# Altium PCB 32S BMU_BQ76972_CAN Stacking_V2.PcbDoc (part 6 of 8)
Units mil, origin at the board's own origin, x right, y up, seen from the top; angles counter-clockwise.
Board outline 7319.29 x 5216.54 mil, 4 copper layers (Top Layer, Layer 1, Layer 2, Bottom Layer), stack 73.068 mil thick; 811 components, 524 nets, 2320 pads, 2669 vias.
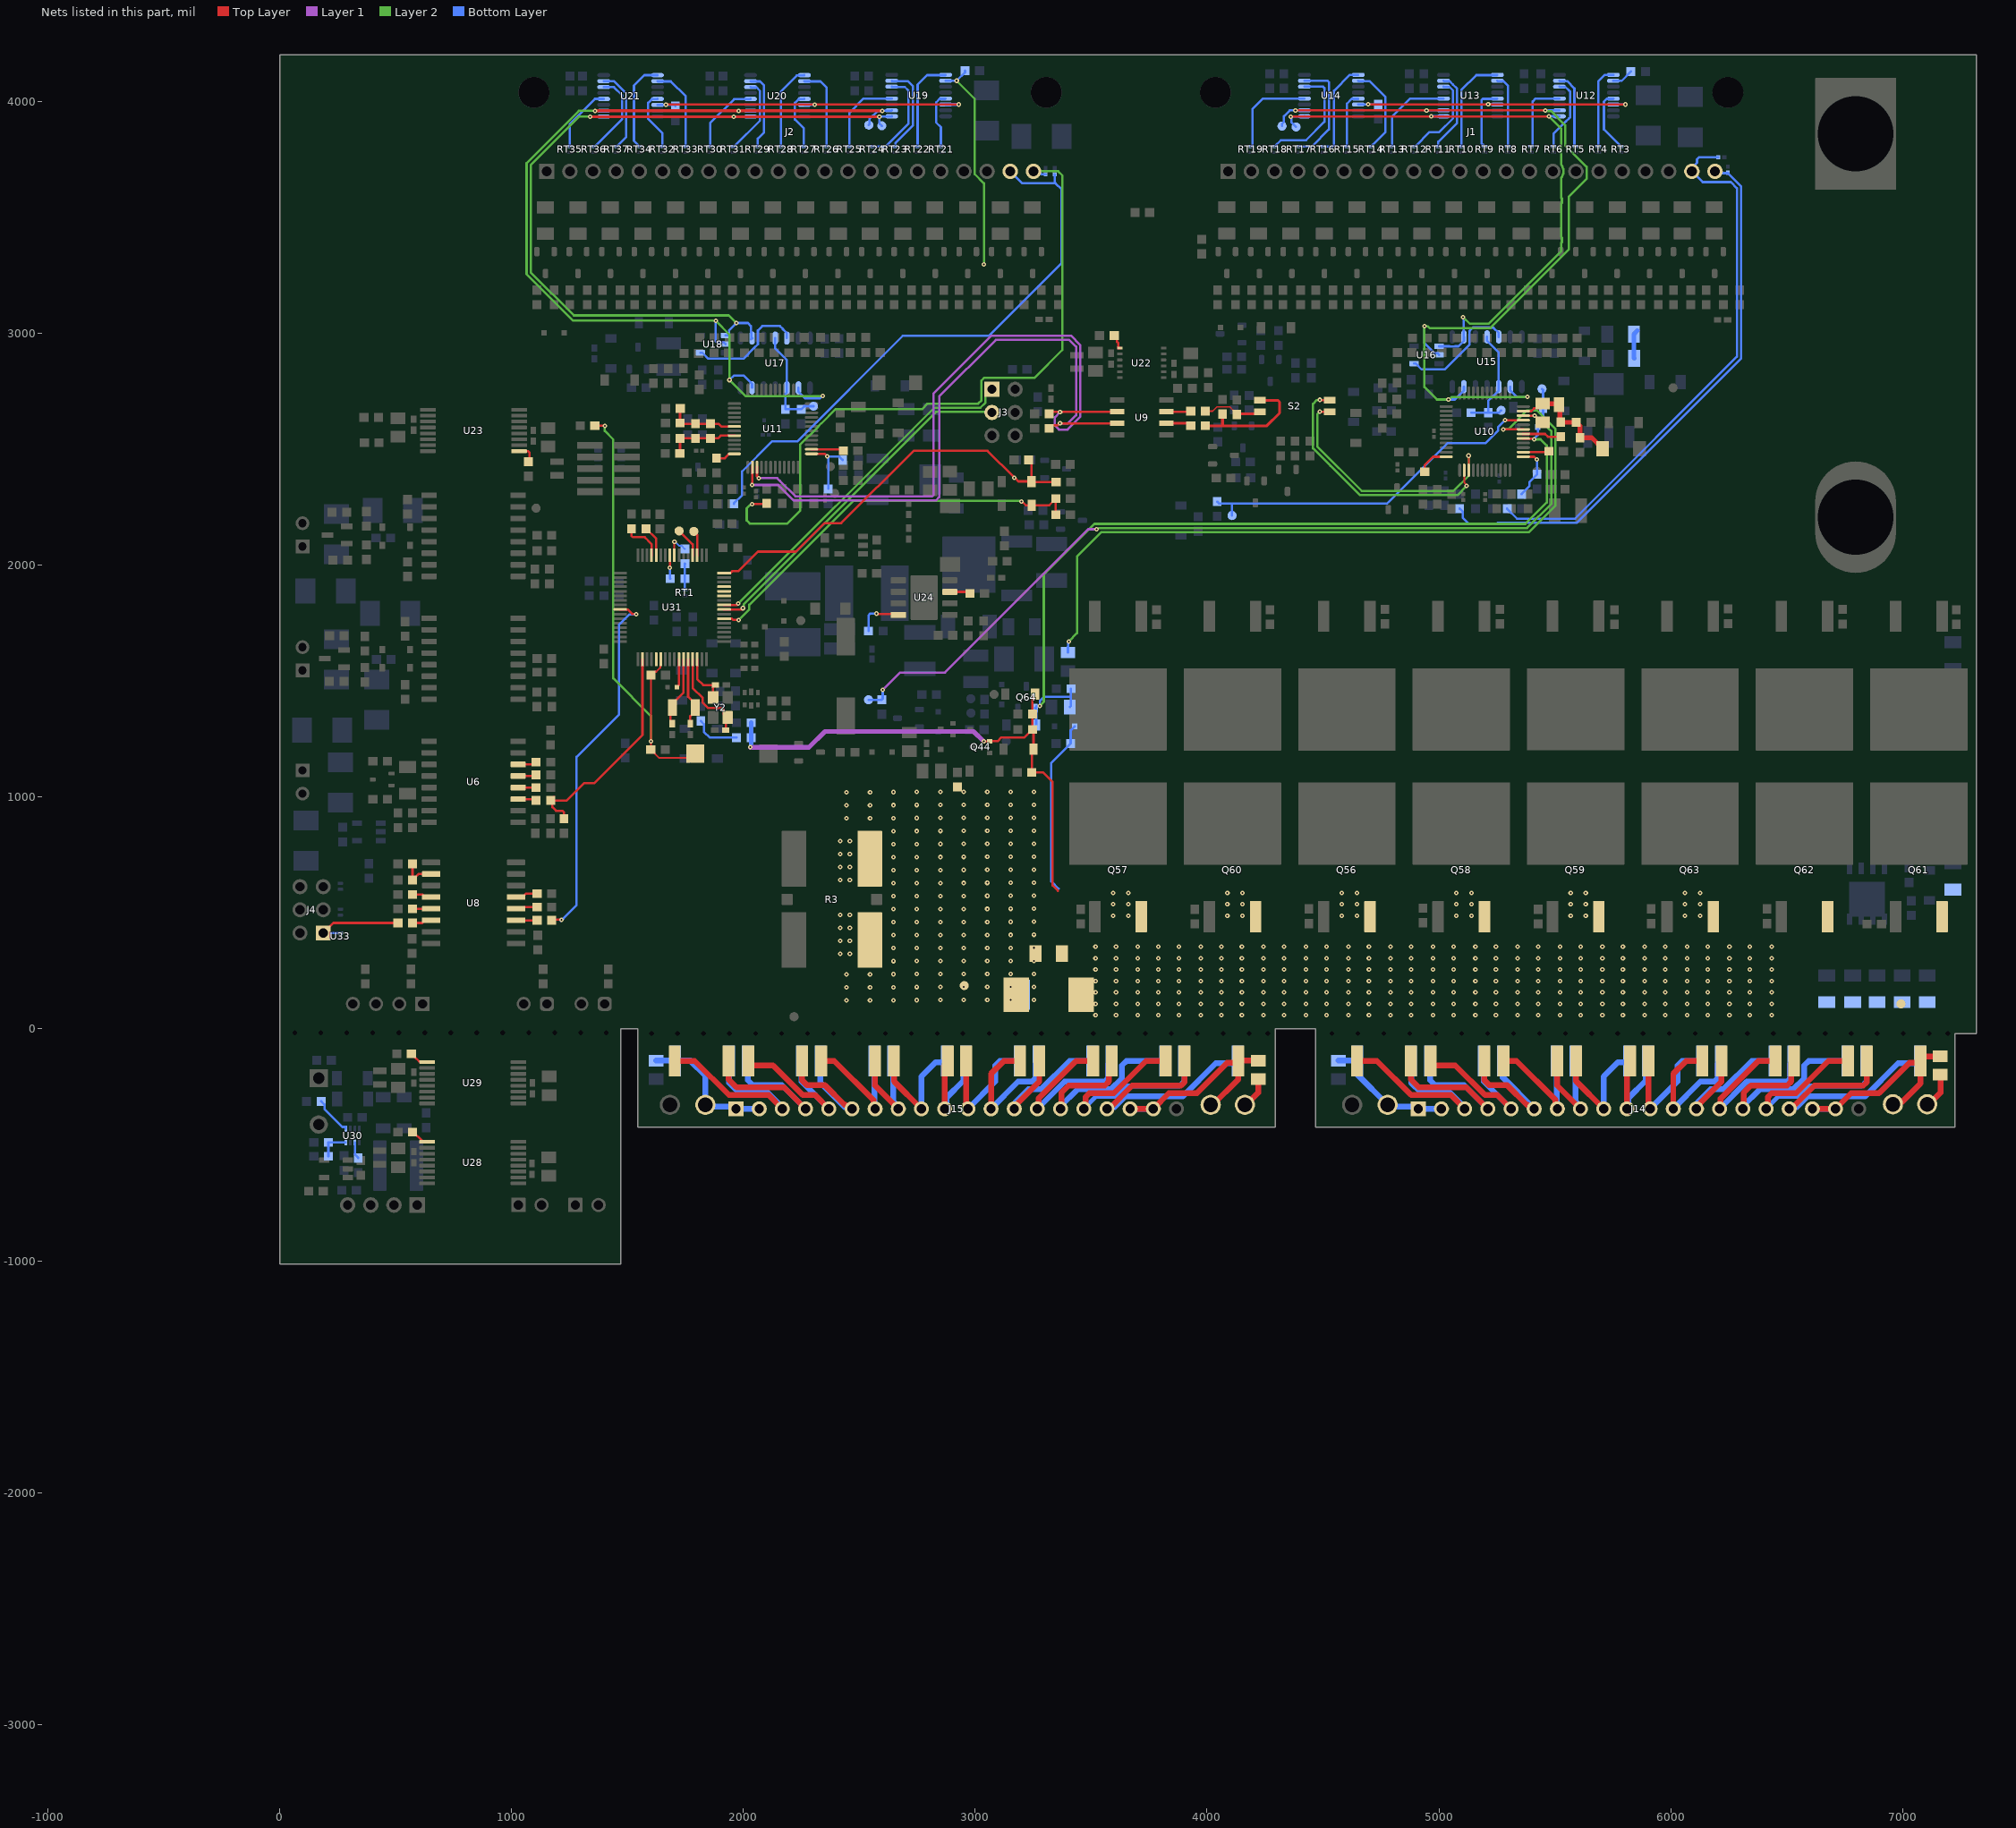
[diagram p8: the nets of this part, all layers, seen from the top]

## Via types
v1: diameter 19.68, hole 7.87, Top Layer to Bottom Layer, tented both sides, 2668 vias
v2: diameter 40, hole 20, Top Layer to Bottom Layer, 1 vias

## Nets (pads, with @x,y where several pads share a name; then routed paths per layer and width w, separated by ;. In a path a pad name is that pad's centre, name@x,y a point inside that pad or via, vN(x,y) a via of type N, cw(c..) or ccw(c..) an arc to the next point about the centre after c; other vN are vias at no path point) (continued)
NetR22_2: R22.2 U31.8 | length 115.6
  Top Layer w8: U31.8@1702.62,2043.51 1702.62,2101 v1(1702.76,2101.14)
  Bottom Layer w8: v1(1702.76,2101.14) 1705.92,2101.14 1722.68,2084.38 1733.72,2084.38 R22.2@1747.87,2070.22
NetR27_2: R27.2 U6.3 | length 79.6
  Top Layer w10: U6.3@1028.41,991.17 1100.41,991.17 R27.2@1105.8,985.78
NetR28_2: R28.2 U6.4 | length 77.5
  Top Layer w10: U6.4@1028.41,1041.17 1105.6,1041.17 R28.2@1105.8,1040.97
NetR30_2: R30.2 U6.5 | length 79.4
  Top Layer w10: U6.5@1028.41,1091.17 1100.82,1091.17 R30.2@1105.8,1096.16
NetR31_2: R31.2 U6.6 | length 81.6
  Top Layer w10: U6.6@1028.41,1141.17 1095.63,1141.17 R31.2@1105.8,1151.34
NetR35_2: R35.2 U8.3 | length 90.8
  Top Layer w10: U8.3@1019.56,468.59 R35.2@1110.35,468.59
NetR36_1: R36.1 U8.14 | length 85.2
  Top Layer w10: R36.1@572.94,457.22 614.49,457.22 625.85,468.59 U8.14@653.41,468.59
NetR37_2: R37.2 U8.4 | length 93.9
  Top Layer w10: U8.4@1019.56,518.59 1047.11,518.59 1054.71,526.18 R37.2@1110.35,526.18
NetR38_1: R38.1 U8.13 | length 80.5
  Top Layer w10: R38.1@572.94,518.59 U8.13@653.41,518.59
NetR39_2: R39.2 U8.12 | length 85.2
  Top Layer w10: R39.2@572.94,579.89 614.55,579.89 625.85,568.59 U8.12@653.41,568.59
NetR40_1: R40.1 U8.5 | length 97.1
  Top Layer w10: U8.5@1019.56,568.59 1047.11,568.59 1062.24,583.71 R40.1@1110.35,583.71
NetR41_1: R41.1 R51.2 S2.2 | length 264.3
  Top Layer w6: R51.2@3992.58,2664.85 4024.59,2664.85 4043.73,2683.99 4097.8,2683.99 4112.62,2669.17 4112.62,2666.8 4126.12,2653.31 R41.1@4128.32,2653.31
  Top Layer w10: R41.1@4128.32,2653.31 4222.93,2653.31 S2.2@4231.33,2661.7
NetR42_1: R42.1 R54.2 S2.1 | length 526.9
  Top Layer w12: R54.2@3992.58,2601.72 4066.99,2601.72 ; R42.1@4066.99,2653.31 4066.99,2601.72 ; S2.1@4231.33,2711.7 4305.27,2711.7 4312.95,2704.02 4312.95,2656.64 4258.04,2601.72 4066.99,2601.72
NetR45_1: R45.1 R52.2 U8.10 | length 160.5
  Top Layer w10: R52.2@572.94,711.67 R45.1@572.94,642.77 573.93,642.77 587.63,656.47 587.63,657.17 599.04,668.59 U8.10@653.41,668.59
NetR51_1: R51.1 U9.7 | length 105.5
  Top Layer w10: U9.7@3824.9,2662.79 3927.52,2662.79 R51.1@3929.58,2664.85
NetR54_1: R54.1 U9.6 | length 109.3
  Top Layer w10: U9.6@3824.9,2612.79 3918.52,2612.79 R54.1@3929.58,2601.72
NetR188_1: R188.1 U10.42 | length 166.3
  Top Layer w10: U10.42@5364.35,2566.69 5458.06,2566.69 5470.16,2554.6 R188.1@5525.62,2554.6
NetR189_1: R189.1 U10.38 | length 111.9
  Top Layer w10: U10.38@5364.35,2487.95 5470.09,2487.95 R189.1@5474.42,2492.28
NetR199_1: R199.1 U11.38 | length 139.6
  Top Layer w10: U11.38@2293.98,2500.45 2424.23,2500.45 R199.1@2430.82,2493.85
NetR201_1: R201.1 R209.2 | length 126
  Bottom Layer w20: R209.2@5842.67,2893.07 5840.96,2894.77 R201.1@5840.96,2997.22 R201.1@5855.94,3012.19
NetR211_1: R211.1 R229.1 U10.37 | length 240.2
  Top Layer w10: U10.37@5364.35,2468.27 5410.87,2468.27 v1(5423.07,2456.06)
  Bottom Layer w10: R211.1@5356.82,2307.06 5356.82,2308.05 5389.95,2341.18 5389.95,2358.41 5423.07,2391.54 R229.1@5423.07,2392.52 v1(5423.07,2456.06)
NetR218_1: R218.1 R248.1 U11.37 | length 287.6
  Top Layer w10: U11.37@2293.98,2480.76 2350.74,2480.76 v1@2362.26,2469.24
  Bottom Layer w10: R218.1@2365.93,2329.54 2365.93,2463.23 2362.26,2466.9 v1(2362.26,2469.52) 2412.63,2469.52 2413.58,2468.57 2414.57,2468.57 2428.27,2454.87 R248.1@2428.27,2453.88
NetR238_1: R238.1 U12.2 | length 92.3
  Bottom Layer w10: U12.2@5752.45,4090.16 5788.56,4090.16 R238.1@5828.28,4129.88
NetR257_2: R257.2 R301.2 TP22.1 U15.3 U15.11 | length 500.1
  Bottom Layer w10: R257.2@5139.35,2657.98 R301.2@5213,2657.98 ; U15.11@5207.86,2985.24 5207.86,2968.5 5257.86,2918.5 U15.3@5257.86,2770.67 5257.86,2753.94 5213,2709.08 R301.2@5213,2657.98 ; TP22.1@5268.67,2668.29 5258.36,2657.98 R301.2@5213,2657.98
NetR260_2: R260.2 R298.2 TP21.1 U17.3 U17.11 | length 457.1
  Bottom Layer w10: U17.11@2137.48,2980.12 2137.48,2935.38 2187.48,2885.38 U17.3@2187.48,2765.55 2187.48,2745.13 2181,2738.65 R298.2@2181,2673.23 R260.2@2249.69,2673.23 2262.63,2686.17 TP21.1@2302.43,2686.17
NetR263_1: R263.1 U24.7 | length 89.1
  Top Layer w10: U24.7@2890.83,1885.41 2970.39,1885.41 R263.1@2977.15,1878.64
NetR295_2: R295.2 U19.6 U20.6 U21.6 | length 1446.2
  Top Layer w10: v1(1666.08,3986.51) 1666.72,3987.15 2928.34,3987.15 v1(2928.98,3987.8)
  Layer 2 w10: v1(1666.08,3986.51) v1@1666.72,3987.15 ; v1@2928.34,3987.15 v1(2928.98,3987.8)
  Bottom Layer w10: U21.6@1629.92,3986.22 1701.66,3986.22 R295.2@1706.98,3980.91
  Bottom Layer w12: U20.6@2263.13,3986.22 v1(2308.18,3986.22) ; U19.6@2872.32,3987.8 v1(2928.98,3987.8)
NetR296_2: R296.2 U12.6 U13.6 U14.6 | length 1285.8
  Top Layer w10: v1@4695.38,3987.94 v1(4695.24,3988.08) v1(5803.88,3987.8)
  Layer 2 w10: v1(4695.24,3988.08) v1@4695.38,3987.94
  Bottom Layer w10: U14.6@4652.35,3987.8 4737.55,3987.8 R296.2@4737.95,3988.19 ; v1(5212.99,3988.21) 5213.2,3988 5252.19,3988 U13.6@5252.4,3987.8 ; U12.6@5752.45,3987.8 v1(5803.88,3987.8)
NetR306_2: R306.2 R307.1 | length 203.4
  Bottom Layer w10: R306.2@1816.22,1328.72 1829.93,1315.02 1829.93,1282.12 1855.52,1256.53 R307.1@1970.48,1256.53
NetR310_2: R310.2 U23.1 | length 88.4
  Top Layer w10: U23.1@1032.89,2492.18 1071.77,2492.18 1077.63,2486.32 1077.63,2463.12 R310.2@1064.87,2450.36
NetR311_2: R311.2 U22.1 | length 68.8
  Top Layer w10: R311.2@3599.45,2991.26 3611.66,2979.05 3611.66,2963.87 3617.65,2957.88 3617.65,2937.91 3618.55,2937.01 U22.1@3625.2,2937.01
NetR318_1: R318.1 U30.6 | length 73.2
  Bottom Layer w10: U30.6@324.27,-489.24 324.27,-541.37 338.47,-555.57 R318.1@338.47,-556.56
NetR319_2: R319.2 U30.1 | length 171
  Bottom Layer w10: R319.2@178.6,-312.46 179.59,-312.46 193.29,-326.16 193.29,-345.54 270.52,-422.78 284,-422.78 284.9,-423.68 U30.1@284.9,-430.97
NetR322_2: R322.2 U28.1 | length 81.7
  Top Layer w10: R322.2@573.46,-441.24 619.29,-487.07 U28.1@636.22,-487.07
NetR323_2: R323.2 U29.1 | length 83.1
  Top Layer w10: R323.2@568.39,-107.1 569.38,-107.1 583.08,-120.8 583.08,-121.79 600.8,-139.51 633.15,-139.51 U29.1@636.22,-142.58
NetR325_2: R325.2 U24.4 | length 201.9
  Top Layer w10: v1(2574.83,1791.75) 2576.69,1789.9 2663.9,1789.9 U24.4@2668.39,1785.41
  Bottom Layer w10: R325.2@2539.76,1716.54 2539.76,1783.92 2547.59,1791.75 v1(2574.83,1791.75)
NetR326_2: R326.2 R327.2 U30.8 | length 134.3
  Bottom Layer w10: R327.2@210.1,-548.68 R326.2@210.1,-489.24 U30.8@284.9,-489.24
NetR330_1: R330.1 U19.2 | length 947.2
  Layer 2 w10: v1(2920.33,4090.16) 2997.7,4012.79 2997.7,3687.91 3037.86,3647.75 v1(3037.86,3297.79)
  Bottom Layer w10: U19.2@2872.32,4090.16 v1(2920.33,4090.16) 2956.14,4125.96 R330.1@2956.14,4133.51
NetR348_2: R348.2 TP24.1 | length 157.8
  Top Layer w25: TP24.1@7093.31,-345.41 7105.17,-333.55 7164.24,-274.48 R348.2@7164.24,-217.04
NetR366_2: R366.2 TP29.1 | length 157.8
  Top Layer w25: TP29.1@4151.52,-339.22 TP29.1@4163.39,-327.36 ; TP29.1@4162.41,-333.54 4221.47,-274.48 R366.2@4221.47,-217.03
NetRT3_2: RT3.2 U12.5 | length 269
  Bottom Layer w10: U12.5@5752.45,4013.39 5750.98,4011.91 5724.16,4011.91 5711.89,3999.64 5711.89,3879.9 RT3.2@5784.71,3807.09
NetRT4_2: RT4.2 U12.1 | length 356.8
  Bottom Layer w10: RT4.2@5687.79,3807.09 5687.79,4087.55 5715.99,4115.75 U12.1@5752.45,4115.75
NetRT5_2: RT5.2 U12.15 | length 331.1
  Bottom Layer w10: U12.15@5520.17,4090.16 5521.65,4088.68 5552.91,4088.68 5584.64,4056.94 5584.64,3808.98 5586.53,3807.09 RT5.2@5588.75,3807.09
NetRT6_2: RT6.2 U12.14 | length 320.8
  Bottom Layer w10: RT6.2@5494.58,3807.09 5494.58,3861.59 5547.75,3914.76 5547.93,3914.76 5560.73,3927.56 5560.73,3927.74 5566.64,3933.65 5566.64,4041.94 5560.73,4047.85 5560.73,4048.03 5545.67,4063.09 5521.65,4063.09 U12.14@5520.17,4064.57
NetRT7_2: RT7.2 U12.12 | length 320.5
  Bottom Layer w10: RT7.2@5397.64,3807.09 5402.56,3807.09 5404.45,3808.98 5404.45,4000.97 5416.87,4013.39 U12.12@5520.17,4013.39
NetRT8_2: RT8.2 U13.2 | length 315.9
  Bottom Layer w10: U13.2@5252.4,4090.16 5253.88,4088.68 5269.43,4088.68 5277.9,4088.68 5297.64,4068.95 RT8.2@5297.64,3807.09
NetRT9_2: RT9.2 U13.5 | length 279.7
  Bottom Layer w10: RT9.2@5197.64,3807.09 5192.71,3807.09 5190.83,3808.98 5190.83,3813.9 5183.46,3821.26 5183.46,4006.05 5189.32,4011.91 5250.93,4011.91 U13.5@5252.4,4013.39
NetRT10_2: RT10.2 U13.1 | length 425.6
  Bottom Layer w10: RT10.2@5097.07,3807.09 5097.07,4050.25 5161.1,4114.27 5250.93,4114.27 U13.1@5252.4,4115.75
NetRT11_2: RT11.2 U13.15 | length 355
  Bottom Layer w10: RT11.2@4997.64,3807.09 4997.64,3827.58 5078.68,3908.62 5078.68,4055.49 5060.68,4073.49 5060.68,4073.62 5045.62,4088.68 5021.6,4088.68 U13.15@5020.12,4090.16
NetRT12_2: RT12.2 U13.14 | length 384.4
  Bottom Layer w10: RT12.2@4894.04,3807.09 4898.96,3807.09 4960.17,3868.29 5001.41,3868.29 5060.68,3927.56 5060.68,4048.03 5045.62,4063.09 5021.6,4063.09 U13.14@5020.12,4064.57
NetRT13_2: RT13.2 U13.12 | length 382.9
  Bottom Layer w10: RT13.2@4797.64,3807.09 4797.64,3935.04 4875.91,4013.31 5020.04,4013.31 U13.12@5020.12,4013.39
NetRT14_2: RT14.2 U14.2 | length 388.3
  Bottom Layer w10: U14.2@4652.35,4090.16 4653.83,4088.68 4701.01,4088.68 4769.65,4020.05 4769.65,3963.12 4769.52,3962.99 4769.52,3950.39 4769.65,3950.27 4769.65,3900.13 4769.52,3900 4769.52,3869.66 4713.76,3813.9 4713.76,3808.98 4711.87,3807.09 RT14.2@4706.95,3807.09
NetRT15_2: RT15.2 U14.5 | length 242.2
  Bottom Layer w10: RT15.2@4603.33,3807.09 4603.33,3990.99 4624.25,4011.91 4650.87,4011.91 U14.5@4652.35,4013.39
NetRT16_2: RT16.2 U14.1 | length 417.8
  Bottom Layer w10: RT16.2@4499.71,3807.09 4542.15,3807.09 4548.01,3812.94 4548.01,4047.32 4616.43,4115.75 U14.1@4652.35,4115.75
NetRT17_2: RT17.2 U14.15 | length 472.8
  Bottom Layer w10: RT17.2@4396.09,3807.09 4453,3807.09 4526.07,3880.16 4526.07,4084.3 4520.21,4090.16 U14.15@4420.07,4090.16
NetRT18_2: RT18.2 U14.14 | length 492.4
  Bottom Layer w10: RT18.2@4292.46,3807.09 4318.81,3833.43 4427.05,3833.43 4506.39,3912.77 4506.39,4058.71 4500.53,4064.57 U14.14@4420.07,4064.57
NetRT19_2: RT19.2 U14.12 | length 409.2
  Bottom Layer w10: RT19.2@4188.84,3807.09 4193.76,3807.09 4195.65,3808.98 4195.65,3966.84 4242.19,4013.39 U14.12@4420.07,4013.39
NetRT21_2: RT21.2 U19.5 | length 245.2
  Bottom Layer w10: RT21.2@2852.05,3807.45 2852.05,3889.58 2831.76,3909.88 2831.76,3996.85 2846.82,4011.91 2870.84,4011.91 U19.5@2872.32,4013.39
NetRT22_2: RT22.2 U19.1 | length 404.7
  Bottom Layer w10: RT22.2@2751.62,3807.09 2751.62,4073.73 2792.16,4114.27 2870.84,4114.27 U19.1@2872.32,4115.75
NetRT23_2: RT23.2 U19.15 | length 393.1
  Bottom Layer w10: U19.15@2640.03,4090.16 2641.51,4088.68 2708.62,4088.68 2731.92,4065.39 2731.92,3897.69 2656.43,3822.2 2656.43,3808.98 2654.54,3807.09 RT23.2@2653.94,3807.09
NetRT24_2: RT24.2 U19.14 | length 417.9
  Bottom Layer w10: RT24.2@2555.91,3807.09 2613.93,3807.09 2711.61,3904.77 2711.61,4048.13 2696.65,4063.09 2641.51,4063.09 U19.14@2640.03,4064.57
NetRT25_2: RT25.2 U19.12 | length 353.5
  Bottom Layer w10: RT25.2@2457.49,3807.09 2457.49,3952.51 2518.36,4013.39 2587.1,4013.39 2587.51,4012.97 2606.43,4012.97 2606.84,4013.39 U19.12@2640.03,4013.39
NetRT26_2: RT26.2 U20.2 | length 360.7
  Bottom Layer w10: U20.2@2263.13,4088.58 2264.6,4087.11 2332.03,4087.11 2359.06,4060.08 RT26.2@2359.06,3807.09
NetRT27_2: RT27.2 U20.5 | length 251.4
  Bottom Layer w10: RT27.2@2260.63,3807.09 2260.63,3885.17 2222.57,3923.23 2222.57,3995.27 2237.63,4010.33 2261.65,4010.33 U20.5@2263.13,4011.81
NetRT28_2: RT28.2 U20.1 | length 366.9
  Bottom Layer w10: RT28.2@2162.42,3807.09 2162.42,4044.4 2230.72,4112.7 2261.65,4112.7 U20.1@2263.13,4114.17
NetRT29_2: RT29.2 U20.15 | length 340.3
  Bottom Layer w10: U20.15@2030.84,4088.58 2032.32,4087.11 2072.12,4087.11 2089.3,4069.93 2089.3,4054.02 2089.4,4053.91 2089.4,3910.6 2089.3,3910.49 2089.3,3867.4 2062.29,3840.4 RT29.2@2062.29,3807.09
NetRT30_2: RT30.2 U20.12 | length 317.2
  Bottom Layer w10: RT30.2@1857.09,3807.09 1857.09,3907.25 1960.18,4010.33 2029.37,4010.33 U20.12@2030.84,4011.81
NetRT31_2: RT31.2 U20.14 | length 337.7
  Bottom Layer w10: RT31.2@1955.52,3807.09 1960.44,3807.09 2071.4,3918.05 2071.4,4046.46 2056.34,4061.52 2032.32,4061.52 U20.14@2030.84,4062.99
NetRT32_2: RT32.2 U21.5 | length 261.4
  Bottom Layer w10: U21.5@1629.92,4011.81 1628.44,4010.33 1604.42,4010.33 1589.36,3995.27 1589.36,3925.99 1602.17,3913.18 1602.34,3913.18 1651.43,3864.09 RT32.2@1651.43,3807.09
NetRT33_2: RT33.2 U21.2 | length 364.4
  Bottom Layer w10: U21.2@1629.92,4088.58 1631.4,4087.11 1687,4087.11 1751.43,4022.67 RT33.2@1751.43,3807.09
NetRT34_2: RT34.2 U21.1 | length 392.5
  Bottom Layer w10: RT34.2@1551.97,3807.09 1528.19,3830.87 1528.19,4069.56 1572.8,4114.17 U21.1@1629.92,4114.17
NetRT35_2: RT35.2 U21.12 | length 287.3
  Bottom Layer w10: RT35.2@1251.43,3807.09 1251.43,3903.19 1360.05,4011.81 U21.12@1397.64,4011.81
NetRT36_2: RT36.2 U21.14 | length 368.1
  Bottom Layer w10: RT36.2@1355.12,3807.09 1360.04,3807.09 1476.83,3923.87 1476.83,4007.65 1476.7,4007.77 1476.7,4028.41 1442.12,4062.99 U21.14@1397.64,4062.99
NetRT37_2: RT37.2 U21.15 | length 366
  Bottom Layer w10: U21.15@1397.64,4088.58 1441.99,4088.58 1494.7,4035.87 1494.7,4015.23 1494.83,4015.1 1494.83,3916.41 1494.7,3916.29 1494.7,3847.73 1454.06,3807.09 RT37.2@1452.64,3807.09
NetU15_12: U15.12 U16.4 | length 512.1
  Bottom Layer w10: U16.4@4892.72,2870.08 4900.6,2870.08 4925.28,2845.39 4976.97,2845.39 4977.1,2845.27 5024.89,2845.27 5132.67,2953.05 5132.67,3011.69 5133.04,3012.07 5133.04,3012.25 5147.58,3026.78 5218.13,3026.78 5220.81,3024.11 5235.72,3024.11 5257.86,3001.97 U15.12@5257.86,2985.24
NetU17_12: U17.12 U18.4 | length 511.2
  Bottom Layer w10: U18.4@1814.61,2916.77 1822.48,2916.77 1848.01,2891.24 2000.24,2891.24 2047.58,2938.57 2047.76,2938.57 2062.67,2953.49 2062.67,3012.97 2081.66,3031.97 2158.12,3031.97 2170.73,3019.36 2170.73,3017.28 2187.48,3000.54 U17.12@2187.48,2980.12
NTC0: C169.1 J1.22 R205.2 | length 2433.8
  Bottom Layer w10: R205.2@5089.75,2244.07 5103.45,2230.37 5103.45,2204.61 5129.32,2178.73 5250.37,2178.73 5254.45,2182.81 5593.87,2182.81 6303.83,2892.76 6303.83,3634.29 6249.66,3688.46 6249.66,3689.63 6247.57,3691.72 6199.16,3691.72 J1.22@6191.28,3699.61
NTC1: C170.1 J1.21 R207.2 | length 2407.2
  Layer 1 w10: J1.21@6091.28,3699.61 J1.21@6091.67,3699.21
  Bottom Layer w10: R207.2@5294.83,2244.07 5294.83,2243.09 5337.11,2200.81 5586.42,2200.81 6285.83,2900.22 6285.83,3626.84 6259.8,3652.86 6138.02,3652.86 J1.21@6091.28,3699.61 6091.28,3714.9 6113.28,3736.91 6113.28,3751.57 6121.55,3759.84 C170.1@6204.85,3759.84
NTC2: C171.1 J2.22 R225.2 | length 2984
  Top Layer w10: v1(2037.4,2263.96) 2097.41,2263.96 R225.2@2100.69,2267.24
  Layer 2 w10: v1(2037.4,2263.96) 2034.78,2263.96 2029.86,2259.04 2027.94,2259.04 2014.56,2245.66 2014.56,2193.39 2027.94,2180.01 2189.17,2180.01 2244.54,2235.38 2244.54,2520.52 2322.33,2598.31 2322.33,2598.49 2335.71,2611.87 2335.89,2611.87 2397.45,2673.43 2770.44,2673.43 2794.42,2697.42 3012.62,2697.42 3026.75,2711.55 3026.75,2797.12 3039.07,2809.44 3256.86,2809.44 3375.98,2928.57 3375.98,3681.1 3357.48,3699.61 J2.22@3251.43,3699.61
  Bottom Layer w10: J2.22@3251.43,3699.61 3273.71,3699.61 3286.7,3686.61 C171.1@3303.71,3686.61
NTC3: C172.1 J2.21 R226.2 | length 2517.4
  Bottom Layer w10: R226.2@1958.92,2264.52 R226.2@1958.92,2265.5 1958.92,2266.49 1994.43,2301.99 1994.43,2405.4 2123.4,2534.37 2231.63,2534.37 2686.97,2989.71 3058.14,2989.71 3372.48,3304.05 3372.48,3622.36 3346.82,3648.02 ; J2.21@3151.43,3699.61 3203.02,3648.02 3346.82,3648.02 ; C172.1@3342.99,3686.61 3342.99,3651.85 3346.82,3648.02
PA2_ROSC: R21.1 U31.42 | length 123.8
  Top Layer w10: R21.1@1713.78,1474.47 1713.78,1474.96 1722.3,1483.48 U31.42@1722.3,1594.69
PA3_LFXIN: C15.2 U31.43 Y1.2 | length 299.1
  Top Layer w10: C15.2@1686.05,1318.77 1686.05,1379.31 Y1.2@1693.6,1386.86 1693.6,1402.61 1741.99,1451 U31.43@1741.99,1594.69
PA4_LFXOUT: C25.2 U31.44 Y1.1 | length 297.4
  Top Layer w10: U31.44@1761.67,1594.69 1761.67,1432.96 1792.02,1402.61 Y1.1@1792.02,1386.86 1792.02,1371.12 1770.53,1349.62 C25.2@1770.53,1318.77
PA5_HFXIN: C16.1 U31.45 Y2.3 | length 406.9
  Top Layer w10: U31.45@1781.36,1594.69 1781.36,1471.03 1824.71,1427.68 1824.71,1407.36 1847.95,1384.12 1908.78,1384.12 1914.64,1378.26 1914.64,1361.19 Y2.3@1932.28,1343.56 1923.96,1335.24 C16.1@1923.96,1289.37
PA6_HFXOUT: C26.1 U31.46 Y2.1 | length 231.9
  Top Layer w10: U31.46@1801.04,1594.69 1801.04,1509.24 1826.8,1483.48 C26.1@1879.38,1483.48 1869.28,1473.39 Y2.1@1869.28,1430.17
PA29: U31.37
PACK+: C111.1 C113.1 D21.2 D23.2 D30.2 D37.1 D48.1 Q44.2 Q56.3 Q57.3 Q58.3 Q59.3 Q60.3 Q61.3 Q62.3 Q63.3 R261.1 R277.2 R278.2 R281.1 R284.2 R285.2 R286.2 R300.2 R303.2 R304.2 R307.2 TP5.1 | length 3080.8
  Top Layer w10: v1(3036.59,1240.35) 3062.12,1240.35 Q44.2@3063.02,1241.25 3096.89,1241.25 3113.13,1257.49 3212.15,1257.49 R261.1@3247.09,1292.43 ; D23.2@3256.06,1441.44 3247.09,1432.46 R304.2@3247.09,1358.27 R261.1@3247.09,1292.43 ; 3356.69,595.7 3333.76,618.63 3333.76,1065.85 3293.07,1106.53 R303.2@3243.94,1106.53 3243.94,1198.95 D21.2@3251.32,1206.33 3251.32,1288.2 R261.1@3247.09,1292.43
  Top Layer w20: D23.2@3258.77,1438.14 D23.2@3258.77,1441.44
  Layer 1 w20: v1(2029.85,1214.94) 2283.23,1214.94 2351.77,1283.47 2993.47,1283.47 v1(3036.59,1240.35)
  Bottom Layer w10: 3359.74,604.69 3328.11,636.32 3328.11,1147.33 R281.1@3411.7,1230.92 3411.7,1287.85 D30.2@3429.13,1305.29
  Bottom Layer w20: v1(2029.85,1214.94) 2033.47,1218.56 R307.2@2033.47,1256.53 R300.2@2033.47,1320.58
  other v1: 3518.94,59.06 3607.52,59.06 3701.6,59.06 3790.18,59.06 3878.76,59.06 3972.83,59.06 4061.42,59.06 4150,59.06 4244.07,59.06 4332.66,59.06 4426.73,59.06 4515.31,59.06 4609.38,59.06 4697.97,59.06 4792.04,59.06 4880.62,59.06 4974.69,59.06 5063.28,59.06 5157.35,59.06 5245.93,59.06 5340,59.06 5428.59,59.06 5522.66,59.06 5611.24,59.06 5705.31,59.06 5793.9,59.06 5887.97,59.06 5976.55,59.06 6070.62,59.06 6159.21,59.06 6253.28,59.06 6341.86,59.06 6435.94,59.06 3518.94,108.27 3607.52,108.27 3701.6,108.27 3790.18,108.27 3878.76,108.27 3972.83,108.27 4061.42,108.27 4150,108.27 4244.07,108.27 4332.66,108.27 4426.73,108.27 4515.31,108.27 4609.38,108.27 4697.97,108.27 4792.04,108.27 4880.62,108.27 4974.69,108.27 5063.28,108.27 5157.35,108.27 5245.93,108.27 5340,108.27 5428.59,108.27 5522.66,108.27 5611.24,108.27 5705.31,108.27 5793.9,108.27 5887.97,108.27 5976.55,108.27 6070.62,108.27 6159.21,108.27 6253.28,108.27 6341.86,108.27 6435.94,108.27 3518.94,157.48 3607.52,157.48 3701.6,157.48 3790.18,157.48 3878.76,157.48 3972.83,157.48 4061.42,157.48 4150,157.48 4244.07,157.48 4332.66,157.48 4426.73,157.48 4515.31,157.48 4609.38,157.48 4697.97,157.48 4792.04,157.48 4880.62,157.48 4974.69,157.48 5063.28,157.48 5157.35,157.48 5245.93,157.48 5340,157.48 5428.59,157.48 5522.66,157.48 5611.24,157.48 5705.31,157.48 5793.9,157.48 5887.97,157.48 5976.55,157.48 6070.62,157.48 6159.21,157.48 6253.28,157.48 6341.86,157.48 6435.94,157.48 3518.94,206.69 3607.52,206.69 3701.6,206.69 3790.18,206.69 3878.76,206.69 3972.83,206.69 4061.42,206.69 4150,206.69 4244.07,206.69 4332.66,206.69 4426.73,206.69 4515.31,206.69 4609.38,206.69 4697.97,206.69 4792.04,206.69 4880.62,206.69 4974.69,206.69 5063.28,206.69 5157.35,206.69 5245.93,206.69 5340,206.69 5428.59,206.69 5522.66,206.69 5611.24,206.69 5705.31,206.69 5793.9,206.69 5887.97,206.69 5976.55,206.69 6070.62,206.69 6159.21,206.69 6253.28,206.69 6341.86,206.69 6435.94,206.69 3518.94,255.91 3607.52,255.91 3701.6,255.91 3790.18,255.91 3878.76,255.91 3972.83,255.91 4061.42,255.91 4150,255.91 4244.07,255.91 4332.66,255.91 4426.73,255.91 4515.31,255.91 4609.38,255.91 4697.97,255.91 4792.04,255.91 4880.62,255.91 4974.69,255.91 5063.28,255.91 5157.35,255.91 5245.93,255.91 5340,255.91 5428.59,255.91 5522.66,255.91 5611.24,255.91 5705.31,255.91 5793.9,255.91 5887.97,255.91 5976.55,255.91 6070.62,255.91 6159.21,255.91 6253.28,255.91 6341.86,255.91 6435.94,255.91 3518.94,305.12 3607.52,305.12 3701.6,305.12 3790.18,305.12 3878.76,305.12 3972.83,305.12 4061.42,305.12 4150,305.12 4244.07,305.12 4332.66,305.12 4426.73,305.12 4515.31,305.12 4609.38,305.12 4697.97,305.12 4792.04,305.12 4880.62,305.12 4974.69,305.12 5063.28,305.12 5157.35,305.12 5245.93,305.12 5340,305.12 5428.59,305.12 5522.66,305.12 5611.24,305.12 5705.31,305.12 5793.9,305.12 5887.97,305.12 5976.55,305.12 6070.62,305.12 6159.21,305.12 6253.28,305.12 6341.86,305.12 6435.94,305.12 3518.94,354.33 3607.52,354.33 3701.6,354.33 3790.18,354.33 3878.76,354.33 3972.83,354.33 4061.42,354.33 4150,354.33 4244.07,354.33 4332.66,354.33 4426.73,354.33 4515.31,354.33 4609.38,354.33 4697.97,354.33 4792.04,354.33 4880.62,354.33 4974.69,354.33 5063.28,354.33 5157.35,354.33 5245.93,354.33 5340,354.33 5428.59,354.33 5522.66,354.33 5611.24,354.33 5705.31,354.33 5793.9,354.33 5887.97,354.33 5976.55,354.33 6070.62,354.33 6159.21,354.33 6253.28,354.33 6341.86,354.33 6435.94,354.33 3594.51,488.49 3659.84,488.49 4087.97,488.49 4153.29,488.49 4581.43,488.49 4646.75,488.49 5074.89,488.49 5140.21,488.49 5568.34,488.49 5633.67,488.49 6061.8,488.49 6127.13,488.49 3594.51,537.71 3659.84,537.71 4087.97,537.71 4153.29,537.71 4581.43,537.71 4646.75,537.71 5074.89,537.71 5140.21,537.71 5568.34,537.71 5633.67,537.71 6061.8,537.71 6127.13,537.71 3594.51,586.92 3659.84,586.92 4087.97,586.92 4153.29,586.92 4581.43,586.92 4646.75,586.92 5074.89,586.92 5140.21,586.92 5568.34,586.92 5633.67,586.92 6061.8,586.92 6127.13,586.92
PACK-: C113.2 D37.2 D48.2 R3.2 R329.1 TP6.1
  other v1: 2445.1,123.39 2546.23,123.69 2647.36,123.98 2748.49,124.27 2849.62,124.56 2950.76,124.86 3051.89,125.15 3153.02,125.44 3254.15,125.73 2445.1,179.5 2546.23,179.79 2647.36,180.08 2748.49,180.38 2849.62,180.67 2950.76,180.96 3051.89,181.25 3153.02,181.55 3254.15,181.84 2445.1,235.6 2546.23,235.9 2647.36,236.19 2748.49,236.48 2849.62,236.77 2950.76,237.07 3051.89,237.36 3153.02,237.65 3254.15,237.95 2647.36,292.29 2748.49,292.59 2849.62,292.88 2950.76,293.17 3051.89,293.47 3153.02,293.76 3254.15,294.05 2417.95,323.8 2459.26,323.8 2647.36,348.4 2748.49,348.69 2849.62,348.99 2950.76,349.28 3051.89,349.57 3153.02,349.86 3254.15,350.16 2417.95,379.91 2459.26,379.91 2647.36,404.51 2748.49,404.8 2849.62,405.09 2950.76,405.38 3051.89,405.68 3153.02,405.97 3254.15,406.26 2417.95,436.01 2459.26,436.01 2647.36,460.61 2748.49,460.9 2849.62,461.2 2950.76,461.49 3051.89,461.78 3153.02,462.07 3254.15,462.37 2417.95,492.12 2459.26,492.12 2647.36,516.72 2748.49,517.01 2849.62,517.3 2950.76,517.59 3051.89,517.89 3153.02,518.18 3254.15,518.47 2647.36,572.82 2748.49,573.11 2849.62,573.41 2950.76,573.7 3051.89,573.99 3153.02,574.29 3254.15,574.58 2647.36,628.93 2748.49,629.22 2849.62,629.51 2950.76,629.81 3051.89,630.1 3153.02,630.39 3254.15,630.68 2417.95,642.05 2459.26,642.05 2647.36,685.03 2748.49,685.33 2849.62,685.62 2950.76,685.91 3051.89,686.2 3153.02,686.5 3254.15,686.79 2417.95,698.16 2459.26,698.16 2647.36,741.14 2748.49,741.43 2849.62,741.72 2950.76,742.02 3051.89,742.31 3153.02,742.6 3254.15,742.89 2417.95,754.26 2459.26,754.26 2647.36,797.24 2748.49,797.54 2849.62,797.83 2950.76,798.12 3051.89,798.41 3153.02,798.71 3254.15,799 2417.95,810.37 2459.26,810.37 2647.36,853.35 2748.49,853.64 2849.62,853.93 2950.76,854.23 3051.89,854.52 3153.02,854.81 3254.15,855.11 2445.1,908.87 2546.23,909.16 2647.36,909.45 2748.49,909.75 2849.62,910.04 2950.76,910.33 3051.89,910.63 3153.02,910.92 3254.15,911.21 2445.1,964.98 2546.23,965.27 2647.36,965.56 2748.49,965.85 2849.62,966.15 2950.76,966.44 3051.89,966.73 3153.02,967.02 3254.15,967.32 2445.1,1021.08 2546.23,1021.37 2647.36,1021.67 2748.49,1021.96 2849.62,1022.25 2950.76,1022.54 3051.89,1022.84 3153.02,1023.13 3254.15,1023.42
PB15: TP8.1 U31.3 | length 108.7
  Top Layer w10: TP8.1@1786.34,2146.12 1801.04,2131.42 U31.3@1801.04,2043.51
PB16: TP3.1 U31.4 | length 129
  Top Layer w10: TP3.1@1722.95,2148.31 1781.36,2089.89 U31.4@1781.36,2043.51
PTC_DA: R22.1 R32.1 RT1.2 | length 114.9
  Bottom Layer w10: RT1.2@1747.87,1895.15 R32.1@1747.87,1941.99 R22.1@1747.87,2007.23 R22.1@1749.84,2005.26
PTC_EN: R32.2 U31.9 | length 97.7
  Top Layer w10: v1@1682.93,1995.99 U31.9@1682.93,2043.51
  Bottom Layer w10: v1(1682.76,1990.25) 1682.76,1944.11 R32.2@1684.88,1941.99 R32.2@1685.87,1941.99
PWM_Fan: J4.1 R36.2 U33.2 | length 414.2
  Top Layer w10: J4.1@187.74,413.68 231.27,457.22 R36.2@509.95,457.22
  Bottom Layer w10: J4.1@187.74,413.68 U33.2@261.69,413.68
PWM_MCU: R35.1 U31.25 | length 1593.5
  Top Layer w10: R35.1@1173.34,468.59 1176.18,471.43 v1(1215.32,471.43) ; U31.25@1468.37,1809.26 1501.36,1809.26 1520.24,1790.38 1520.24,1790.2 1535.22,1790.2 v1(1537.08,1788.35)
  Bottom Layer w10: v1@1213.29,466.31 1216.87,469.88 1216.87,470.36 1222.78,476.28 1223.26,476.28 1280.84,533.86 1280.84,1173.01 1462.95,1355.12 1462.95,1742.27 1509.03,1788.35 v1(1537.08,1788.35)
REG18_BOT: C71.1 U11.24 | length 84.6
  Top Layer w10: C71.1@1884.49,2461.86 1919.76,2461.86 1938.66,2480.76 U11.24@1961.3,2480.76
REG18_TOP: C67.1 U10.24 | length 135.9
  Top Layer w10: C67.1@4938.98,2403.83 4938.98,2432.01 4975.24,2468.27 U10.24@5031.67,2468.27
RST_MCU: C14.1 R8.1 R305.2 S1.2 U31.38 | length 2103.6
  Top Layer w8: C14.1@1597.44,1207.68 1601.4,1211.64 v1(1601.4,1241.17) R8.1@1601.4,1526.2 1616.1,1540.91 1623.74,1540.91 1635.05,1552.22 1641.78,1558.95 1641.78,1592.91 U31.38@1643.56,1594.69 ; C14.1@1600.39,1204.72 1601.38,1204.72 1637.54,1168.56 S1.2@1792.95,1168.56
  Top Layer w10: R305.2@1359.6,2601.68 v1(1401.94,2601.68)
  Layer 2 w10: v1(1401.94,2601.68) 1401.94,2579.17 1438.69,2542.41 1438.69,1512.36 1601.4,1349.66 v1(1601.4,1241.17)
RXD: R5.1 R27.1 U31.34 | length 967
  Top Layer w10: R27.1@1175.94,993.09 R27.1@1182.34,999.48 ; R5.1@1226.55,907.34 1226.55,933.88 1219.26,941.17 1192.09,941.17 1176.18,957.08 1176.18,978.39 R27.1@1168.79,985.78 1238.29,985.78 1313.34,1060.82 1357.75,1060.82 1564.82,1267.9 U31.34@1564.82,1594.69
SCL: R53.2 U9.3 U11.26 | length 2737.2
  Top Layer w10: v1(2037.4,2346.46) 2039.05,2348.11 U11.26@2039.05,2422.69 ; R53.2@3319.03,2591.03 3332.73,2604.73 3356.52,2604.73 3363.99,2612.2 v1(3366.14,2612.2) 3611.72,2612.2 U9.3@3612.3,2612.79
  Layer 1 w10: v1(2037.4,2346.46) 2150.3,2346.46 2162.94,2333.82 2217.19,2279.57 2830.5,2279.57 2845.04,2294.11 2845.04,2728.76 3088.72,2972.44 3405.51,2972.44 3435.04,2942.91 3435.04,2647.64 3399.61,2612.2 v1(3366.14,2612.2)
SCL_MCU: J3.1 U31.57 | length 1589.7
  Top Layer w10: U31.57@1917.19,1828.94 1972.65,1828.94 v1(1978.35,1834.65)
  Layer 2 w10: v1(1978.35,1834.65) 2823.12,2679.42 3022.57,2679.42 3044.75,2701.6 3044.75,2731.78 3093.03,2780.06 J3.1@3095.23,2780.06
SCL_TOPAFE: S2.4 U10.26 | length 1109.3
  Top Layer w8: U10.26@5109.43,2410.2 5109.43,2356.61 5120.32,2345.72 v1(5120.32,2342.56)
  Top Layer w10: v1(4487.26,2714.03) 4489.55,2711.73 4506.29,2711.73 4506.33,2711.7 S2.4@4531.33,2711.7
  Layer 2 w10: v1(4487.26,2714.03) 4485.66,2712.44 4473.72,2712.44 4457.32,2696.03 4457.32,2504.25 4532.21,2429.36 4532.95,2429.36 4659.56,2302.74 5080.51,2302.74 v1(5120.32,2342.56)
SCLK: U31.61
SDA: R46.2 U9.2 U11.27 | length 2844.1
  Top Layer w10: U11.27@2058.74,2422.69 2058.74,2384.17 v1(2066.93,2375.98) ; R46.2@3319.03,2653.49 3326.96,2661.42 v1(3366.14,2661.42) 3367.51,2662.79 U9.2@3612.3,2662.79
  Layer 1 w10: v1(2066.93,2375.98) 2146.05,2375.98 2157.58,2364.46 2157.76,2364.46 2224.65,2297.57 2815.07,2297.57 2820.93,2303.43 2820.93,2741.75 3069.62,2990.44 3412.97,2990.44 3453.04,2950.37 3453.04,2640.18 3398.26,2585.4 3360.64,2585.4 3343.3,2602.74 3343.3,2638.57 v1(3366.14,2661.42)
SDA_MCU: J3.3 U31.56 | length 1518.3
  Top Layer w10: U31.56@1917.19,1809.26 1992.33,1809.26 v1(1998.03,1814.96)
  Layer 2 w10: v1(1998.03,1814.96) 1999.88,1816.81 1999.88,1823.88 2001.19,1825.18 2001.19,1832.03 2830.57,2661.42 J3.3@3074.39,2661.42
SDA_TOPAFE: S2.3 U10.27 | length 1110
  Top Layer w8: v1(5128.23,2472.93) 5129.12,2472.05 U10.27@5129.12,2410.2
  Top Layer w10: v1(4487.26,2662.79) 4488.35,2661.7 S2.3@4531.33,2661.7
  Layer 2 w10: v1(4487.26,2662.79) 4486.02,2662.79 4475.32,2652.09 4475.32,2512.45 4667.02,2320.74 5063.09,2320.74 5128.23,2385.88 v1(5128.23,2472.93)
SDI: U31.60
SDO: U31.59
SEL0_BOT: TP15.1 U17.2 U17.6 U18.2 U19.10 U20.10 U21.10 | length 4347.5
  Top Layer w12: v1(1360.04,3960.63) v1(1979.79,3960.63) v1(2599.13,3960.63)
  Layer 2 w10: v1(1360.04,3960.63) 1290.77,3960.63 1064.8,3734.66 1064.8,3256.33 1266.01,3055.12 v1(1880.9,3055.12) 1940.08,2995.94 v1(1940.08,2799.21) 2008.98,2730.31 v1(2342.73,2730.31)
  Bottom Layer w10: v1(1360.04,3960.63) U21.10@1397.64,3960.63 ; v1(1880.9,3055.12) 1880.9,2966.84 1886.76,2960.98 1916.06,2960.98 U18.2@1922.87,2954.17 ; v1(1940.08,2799.21) 1959.76,2818.9 2000.87,2818.9 2037.48,2782.28 U17.6@2037.48,2765.55 ; v1@1987.48,3960.63 U20.10@2030.84,3960.63 ; U17.2@2237.48,2765.55 2237.48,2748.82 2265.67,2720.63 2330.43,2720.63 2340.11,2730.31 v1(2342.73,2730.31) ; TP15.1@2540.79,3899.06 2544.07,3902.35 2544.07,3924.82 2578.03,3958.78 2597.27,3958.78 v1(2599.13,3960.63) 2599.91,3961.42 2639.25,3961.42 U19.10@2640.03,3962.2
SEL0_TOP: TP16.1 U12.10 U13.10 U14.10 U15.2 U15.6 U16.2 | length 4031.3
  Top Layer w10: v1(4381.33,3962.2) v1(4946.86,3962.2) ; 4845.72,3962.2 v1(4946.86,3962.2) ; v1(5459.09,3962.2) v1(4946.86,3962.2)
  Layer 2 w10: v1@4937.4,3027.64 4937.4,2768.94 4991.28,2715.07 v1(5041.35,2715.07) 5043.97,2715.07 5055.28,2726.38 v1(5381.31,2726.38) ; v1(4937.4,3031.5) 4937.67,3031.23 4952.26,3031.23 4959.89,3023.6 5221.68,3023.6 5560.27,3362.19 5560.27,3590 5637.54,3667.28 5637.54,3718.77 5544.97,3811.34 5544.97,3898.14 5483.66,3959.46 5468.69,3959.46 5467.79,3960.35 5460.94,3960.35 v1(5459.09,3962.2)
  Bottom Layer w10: TP16.1@4323.5,3894.63 4323.5,3904.38 4331.85,3912.73 4331.85,3937.55 4356.48,3962.18 v1(4381.33,3962.2) ; v1(4381.33,3962.2) U14.10@4420.07,3962.2 ; v1(4937.4,3031.5) 4937.4,2958.65 4981.76,2914.29 4994.18,2914.29 U16.2@5000.99,2907.48 ; v1(4946.86,3962.2) U13.10@5020.12,3962.2 ; v1(5041.35,2715.07) 5068.99,2715.07 5107.86,2753.94 U15.6@5107.86,2770.67 ; U15.2@5307.86,2770.67 5307.86,2753.94 5335.41,2726.38 v1(5381.31,2726.38) ; v1(5459.09,3962.2) U12.10@5520.17,3962.2
SEL1_BOT: TP1.1 U17.9 U18.1 U19.9 U20.9 U21.9 | length 3469.6
  Top Layer w12: v1(1338.58,3935.04) v1(1958.66,3935.04) v1(2586.59,3935.04)
  Layer 2 w10: v1(1338.58,3935.04) 1290.63,3935.04 1082.8,3727.21 1082.8,3263.78 1268.63,3077.96 1936.92,3077.96 v1(1969.61,3045.28)
  Bottom Layer w10: v1(1338.58,3935.04) U21.9@1397.64,3935.04 ; U18.1@1922.87,2991.57 1930.75,2991.57 1937.56,2998.38 1937.56,3013.23 v1(1969.61,3045.28) 2019.37,3045.28 2032.68,3031.97 2032.68,3005.34 2034.87,3003.14 U17.9@2034.87,2976.64 ; v1(1958.66,3935.04) U20.9@2030.84,3935.04 ; U17.9@2032.68,2974.44 U17.9@2034.87,2976.64 ; U17.9@2037.48,2980.12 2037.48,2979.24 U17.9@2034.87,2976.64 ; TP1.1@2597.27,3895.98 2586.59,3906.66 v1(2586.59,3935.04) 2587.38,3935.83 2639.25,3935.83 U19.9@2640.03,3936.61
SEL1_TOP: TP18.1 U12.9 U13.9 U14.9 U15.9 U16.1 | length 2726.4
  Top Layer w10: v1(4361.64,3935.04) 4362.43,3935.83 4966.93,3936.25 v1(5474.2,3936.61)
  Layer 2 w10: v1(4361.64,3935.04) v1@4362.43,3935.83 ; v1(5104.72,3070.87) 5133.99,3041.6 5214.22,3041.6 5526.97,3354.35 5526.97,3390.11 5530.75,3393.88 5530.75,3412.81 5526.97,3416.59 5526.97,3559.4 5530.75,3563.18 5530.75,3582.1 5526.97,3585.88 5526.97,3670.17 ccw(c5491.28,3699.61) 5526.97,3729.04 5526.97,3883.84 v1(5474.2,3936.61)
  Bottom Layer w10: TP18.1@4384.07,3890.72 4363.49,3911.3 4363.49,3933.18 v1(4361.64,3935.04) 4362.43,3935.83 4419.28,3935.83 U14.9@4420.07,3936.61 ; v1(4966.93,3936.61) U13.9@5020.12,3936.61 ; U16.1@5000.99,2944.88 5046.39,2944.88 5047.58,2943.69 5068.13,2943.69 5069.32,2944.88 5084.23,2944.88 5107.86,2968.5 U15.9@5107.86,2985.24 5106.29,2986.8 5106.29,3069.3 v1(5104.72,3070.87) ; v1(5474.2,3936.61) U12.9@5520.17,3936.61
Sim_Cell0: J15.1 J15.2 R349.2 R365.1 TP25.1@1836.32,-327.35 | length 600.9
  Bottom Layer w25: R365.1@1624.02,-137.03 1771.65,-137.03 1836.32,-201.7 TP25.1@1836.32,-327.35 ; TP25.1@1836.32,-334.51 1958.52,-334.51 J15.1@1968.36,-344.36 J15.2@2068.36,-344.36
Sim_Cell1: J15.3 R349.1 R350.2 | length 952.8
  Top Layer w25: R350.2@1704.19,-137.66 1790.06,-137.66 1937.7,-285.3 2109.31,-285.3 J15.3@2168.36,-344.36
  Bottom Layer w25: R349.1@1937.88,-110.24 R349.1@1937.88,-137.66 1937.88,-232.38 1980.96,-275.46 2106.34,-275.46 2168.36,-337.48 J15.3@2168.36,-344.36
Sim_Cell2: J15.4 R350.1 R351.2 | length 875.8
  Top Layer w25: R350.1@1936.47,-137.66 1936.47,-217.94 1970.15,-251.62 2175.62,-251.62 J15.4@2268.36,-344.36
  Bottom Layer w25: R351.2@2019.15,-110.24 R351.2@2019.15,-137.66 2019.15,-221.36 2040.25,-242.46 2166.46,-242.46 J15.4@2268.36,-344.36
Sim_Cell3: J15.5 R351.1 R352.2 | length 687.7
  Top Layer w25: R352.2@2021.39,-137.66 2041.07,-157.35 2128.02,-157.35 2255.98,-285.3 2309.31,-285.3 J15.5@2368.36,-344.36
  Bottom Layer w25: R351.1@2251.44,-137.66 2251.44,-227.43 J15.5@2368.36,-344.36
Sim_Cell4: J15.6 R352.1 R353.2 | length 626.8
  Top Layer w25: R352.1@2253.67,-137.66 2253.67,-221.74 2274.85,-242.92 2351.97,-242.92 2436.4,-327.35 2440.55,-327.35 2457.55,-344.36 J15.6@2468.36,-344.36
  Bottom Layer w25: R353.2@2332.71,-137.66 2332.71,-233.14 2436.28,-336.71 2460.72,-336.71 J15.6@2468.36,-344.36
Sim_Cell5: J15.7 R353.1 R354.2 | length 544.2
  Top Layer w25: R354.2@2335.78,-137.67 2392.24,-137.67 2560.72,-306.14 2560.72,-336.71 J15.7@2568.36,-344.36
  Bottom Layer w25: R353.1@2564.99,-137.66 2564.99,-340.99 J15.7@2568.36,-344.36
Sim_Cell6: J15.8 R354.1 R355.2 | length 464.1
  Top Layer w25: R354.1@2568.06,-137.67 2568.06,-244.05 J15.8@2668.36,-344.36
  Bottom Layer w25: R355.2@2646.26,-137.66 2646.26,-311.45 2668.36,-333.54 J15.8@2668.36,-344.36
Sim_Cell7: J15.9 R355.1 R356.2 | length 533.3
  Top Layer w25: R356.2@2649.53,-137.67 2649.53,-225.52 J15.9@2768.36,-344.36
  Bottom Layer w25: J15.9@2768.36,-344.36 2768.36,-205.06 2830.1,-143.32 2872.89,-143.32 R355.1@2878.55,-137.66
Sim_Cell8: J15.10 R356.1 R357.2 | length 456.8
  Top Layer w25: J15.10@2868.36,-344.36 2868.36,-206.74 2868.72,-206.38 2868.72,-150.76 R356.1@2881.81,-137.67
  Bottom Layer w25: J15.10@2868.36,-344.36 2875.32,-337.4 2875.32,-297.64 2949.78,-223.18 2949.78,-147.7 R357.2@2959.82,-137.66
Sim_Cell9: J15.11 R357.1 R358.2 | length 559.2
  Top Layer w25: R358.2@2961.41,-137.67 2961.41,-337.4 J15.11@2968.36,-344.36
  Bottom Layer w25: J15.11@2968.36,-344.36 3086.54,-226.18 3086.54,-157.35 3106.23,-137.66 R357.1@3192.1,-137.66
Sim_Cell10: J15.12 R358.1 R359.2 | length 626.4
  Top Layer w25: J15.12@3068.36,-344.36 3068.36,-193.24 3123.94,-137.67 R358.1@3193.69,-137.67
  Bottom Layer w25: J15.12@3068.36,-344.36 3185.29,-227.43 3245.64,-227.43 3260.28,-212.79 3260.28,-150.75 R359.2@3273.37,-137.66
Sim_Cell11: J15.13 R359.1 R360.2 | length 687.9
  Top Layer w25: J15.13@3168.36,-344.36 3168.36,-334.86 3276.57,-226.65 R360.2@3276.57,-137.67
  Bottom Layer w25: J15.13@3168.36,-344.36 3176.01,-336.71 3176.01,-313.74 3229.31,-260.43 3284.29,-260.43 3407.06,-137.66 R359.1@3505.66,-137.66
Sim_Cell12: J15.14 R360.1 R361.2 | length 790.1
  Top Layer w25: J15.14@3268.36,-344.36 3272.79,-339.93 3272.79,-299.82 3434.94,-137.67 R360.1@3508.85,-137.67
  Bottom Layer w25: J15.14@3268.36,-344.36 3385.29,-227.43 3559.19,-227.43 3573.84,-212.79 3573.84,-150.75 R361.2@3586.93,-137.66
Sim_Cell13: J15.15 R361.1 R362.2 | length 965.3
  Top Layer w25: J15.15@3368.36,-344.36 3372.3,-340.42 3372.3,-274.38 3402.62,-244.05 3559.03,-244.05 3577.56,-225.52 3577.56,-149.35 R362.2@3589.25,-137.67
  Bottom Layer w25: J15.15@3368.36,-344.36 3368.36,-333.54 3441.47,-260.43 3529.91,-260.43 3585.67,-260.43 3633.02,-213.08 3633.02,-157.32 3652.67,-137.66 R361.1@3819.21,-137.66
Sim_Cell14: J15.16 R362.1 R363.2 | length 1033.7
  Top Layer w25: J15.16@3468.36,-344.36 3476.01,-336.71 3476.01,-293.47 3492.42,-277.05 3597.83,-277.05 3737.22,-137.67 R362.1@3821.54,-137.67
  Bottom Layer w20: J15.16@3468.36,-344.36 3521.79,-290.93 3603.73,-290.93 3648.73,-245.93 3880.73,-245.93 3900.48,-226.18 R363.2@3900.48,-137.66
Sim_Cell15: J15.17 R363.1 R364.2 | length 1123.7
  Top Layer w25: J15.17@3568.36,-344.36 3577.19,-344.36 3677.5,-244.05 3888.02,-244.05 3902.66,-229.41 R364.2@3902.66,-137.67
  Bottom Layer w25: J15.17@3568.36,-344.36 3576.01,-336.71 3601.08,-336.71 3646.42,-291.38 3894.79,-291.38 4038.27,-147.91 4122.52,-147.91 R363.1@4132.76,-137.66
Sim_Cell16: J15.18 J15.19 R364.1 R366.1 TP27.1 | length 1003.3
  Top Layer w25: J15.18@3668.36,-344.36 J15.19@3768.36,-344.36 3835.67,-277.05 3955.97,-277.05 4086.5,-146.52 4126.09,-146.52 R364.1@4134.95,-137.67 ; TP27.1@4010.92,-333.54 4018.44,-333.54 4134.95,-217.03 4134.95,-146.52 R364.1@4134.95,-137.67 ; R366.1@4221.47,-137.03 4135.58,-137.03 R364.1@4134.95,-137.67 ; R366.1@4230.34,-137.03 R366.1@4239.29,-145.98
  Bottom Layer w25: J15.18@3668.36,-344.36 J15.19@3768.36,-344.36
Sim_Cell16B: J14.1 J14.2 R331.2 R347.1 TP9.1 | length 561.8
  Bottom Layer w25: R347.1@4566.78,-137.04 4647.73,-137.04 R331.2@4648.36,-137.66 4648.36,-196.64 TP9.1@4779.08,-327.36 ; TP9.1@4779.08,-334.52 4901.28,-334.52 J14.1@4911.13,-344.36 J14.2@5011.13,-344.36
Sim_Cell17: J14.3 R331.1 R332.2 | length 952.8
  Top Layer w25: R332.2@4646.95,-137.67 4732.83,-137.67 4880.46,-285.3 5052.07,-285.3 J14.3@5111.13,-344.36
  Bottom Layer w25: R331.1@4880.65,-110.24 R331.1@4880.65,-137.66 4880.65,-232.38 4923.73,-275.46 5049.11,-275.46 5111.13,-337.48 J14.3@5111.13,-344.36
Sim_Cell18: J14.4 R332.1 R333.2 | length 875.8
  Top Layer w25: R332.1@4879.24,-137.67 4879.24,-217.94 4912.92,-251.62 5118.39,-251.62 J14.4@5211.13,-344.36
  Bottom Layer w25: R333.2@4961.92,-110.24 R333.2@4961.92,-137.66 4961.92,-221.36 4983.02,-242.46 5109.23,-242.46 J14.4@5211.13,-344.36
Sim_Cell19: J14.5 R333.1 R334.2 | length 687.7
  Top Layer w25: R334.2@4964.15,-137.67 4983.84,-157.35 5070.79,-157.35 5198.74,-285.3 5252.07,-285.3 J14.5@5311.13,-344.36
  Bottom Layer w25: R333.1@5194.2,-137.66 5194.2,-227.43 J14.5@5311.13,-344.36
Sim_Cell20: J14.6 R334.1 R335.2 | length 612.4
  Top Layer w25: R334.1@5196.44,-137.67 5196.44,-221.75 5217.62,-242.92 5294.73,-242.92 5379.16,-327.36 5383.31,-327.36 5400.31,-344.36 J14.6@5411.13,-344.36
  Bottom Layer w25: R335.2@5275.47,-137.66 5275.47,-208.7 J14.6@5411.13,-344.36
Sim_Cell21: J14.7 R335.1 R336.2 | length 544.2
  Top Layer w25: R336.2@5278.54,-137.67 5335,-137.67 5503.48,-306.15 5503.48,-336.71 J14.7@5511.13,-344.36
  Bottom Layer w25: R335.1@5507.76,-137.66 5507.76,-340.99 J14.7@5511.13,-344.36
Sim_Cell22: J14.8 R336.1 R337.2 | length 464.1
  Top Layer w25: R336.1@5510.82,-137.67 5510.82,-244.06 J14.8@5611.13,-344.36
  Bottom Layer w25: R337.2@5589.03,-137.66 5589.03,-311.45 5611.13,-333.55 J14.8@5611.13,-344.36
Sim_Cell23: J14.9 R337.1 R338.2 | length 533.3
  Top Layer w25: R338.2@5592.29,-137.67 5592.29,-225.52 J14.9@5711.13,-344.36
  Bottom Layer w25: J14.9@5711.13,-344.36 5711.13,-205.06 5772.87,-143.32 5815.66,-143.32 R337.1@5821.31,-137.66
Sim_Cell24: J14.10 R338.1 R339.2 | length 456.8
  Top Layer w25: J14.10@5811.13,-344.36 5811.13,-206.74 5811.49,-206.38 5811.49,-150.76 R338.1@5824.58,-137.67
  Bottom Layer w25: J14.10@5811.13,-344.36 5818.08,-337.4 5818.08,-297.64 5892.55,-223.18 5892.55,-147.7 R339.2@5902.58,-137.66
Sim_Cell25: J14.11 R339.1 R340.2 | length 559.2
  Top Layer w25: R340.2@5904.17,-137.67 5904.17,-337.4 J14.11@5911.13,-344.36
  Bottom Layer w25: J14.11@5911.13,-344.36 6029.31,-226.18 6029.31,-157.35 6048.99,-137.66 R339.1@6134.87,-137.66
Sim_Cell26: J14.12 R340.1 R341.2 | length 626.4
  Top Layer w25: J14.12@6011.13,-344.36 6011.13,-193.24 6066.7,-137.67 R340.1@6136.46,-137.67
  Bottom Layer w25: J14.12@6011.13,-344.36 6128.05,-227.43 6188.4,-227.43 6203.05,-212.79 6203.05,-150.76 R341.2@6216.14,-137.66
Sim_Cell27: J14.13 R341.1 R342.2 | length 687.9
  Top Layer w25: J14.13@6111.13,-344.36 6111.13,-334.86 6219.34,-226.65 R342.2@6219.34,-137.67
  Bottom Layer w25: J14.13@6111.13,-344.36 6118.77,-336.71 6118.77,-313.74 6172.08,-260.43 6227.05,-260.43 6349.82,-137.66 R341.1@6448.42,-137.66
Sim_Cell28: J14.14 R342.1 R343.2 | length 790.1
  Top Layer w25: J14.14@6211.13,-344.36 6215.55,-339.93 6215.55,-299.82 6377.7,-137.67 R342.1@6451.62,-137.67
  Bottom Layer w25: J14.14@6211.13,-344.36 6328.05,-227.43 6501.96,-227.43 6516.6,-212.79 6516.6,-150.76 R343.2@6529.69,-137.66
Sim_Cell29: J14.15 R343.1 R344.2 | length 965.3
  Top Layer w25: J14.15@6311.13,-344.36 6315.06,-340.42 6315.06,-274.38 6345.39,-244.06 6501.8,-244.06 6520.33,-225.52 6520.33,-149.35 R344.2@6532.02,-137.67
  Bottom Layer w25: J14.15@6311.13,-344.36 6311.13,-333.55 6384.24,-260.43 6472.67,-260.43 6528.43,-260.43 6575.78,-213.09 6575.78,-157.32 6595.44,-137.66 R343.1@6761.98,-137.66
Sim_Cell30: J14.16 R344.1 R345.2 | length 1033.7
  Top Layer w25: J14.16@6411.13,-344.36 6418.77,-336.71 6418.77,-293.47 6435.18,-277.06 6540.59,-277.06 6679.98,-137.67 R344.1@6764.3,-137.67
  Bottom Layer w20: J14.16@6411.13,-344.36 6464.55,-290.93 6546.49,-290.93 6591.49,-245.93 6823.49,-245.93 6843.25,-226.18 R345.2@6843.25,-137.66
Sim_Cell31: J14.17 R345.1 R346.2 | length 1123.7
  Top Layer w25: J14.17@6511.13,-344.36 6519.96,-344.36 6620.26,-244.06 6830.78,-244.06 6845.43,-229.41 R346.2@6845.43,-137.67
  Bottom Layer w25: J14.17@6511.13,-344.36 6518.77,-336.71 6543.85,-336.71 6589.18,-291.38 6837.56,-291.38 6981.03,-147.91 7065.29,-147.91 R345.1@7075.53,-137.66
Sim_Cell32: J14.18 J14.19 R346.1 R348.1 TP12.1 | length 1003.1
  Top Layer w25: J14.18@6611.13,-344.36 J14.19@6711.13,-344.36 6778.43,-277.06 6898.73,-277.06 7029.26,-146.52 7068.86,-146.52 R346.1@7077.71,-137.67 ; TP12.1@6958.59,-324.8 6970.45,-312.94 6999.97,-312.94 7077.71,-235.2 R346.1@7077.71,-137.67 ; R348.1@7162.65,-117.32 7161.87,-118.11 7090.8,-118.11 7077.71,-131.2 R346.1@7077.71,-137.67
  Bottom Layer w25: J14.18@6611.13,-344.36 J14.19@6711.13,-344.36
SRN: C73.1 C77.2 C89.2 R251.2 U11.20 | length 304.6
  Top Layer w10: C77.2@1726,2482.58 1726.89,2483.48 R251.2@1726.89,2547.41 C89.2@1793.1,2547.41 1890.37,2547.41 1902.47,2559.5 U11.20@1961.3,2559.5
SRP: C72.1 C73.2 C89.1 R239.2 U11.18 | length 304.4
  Top Layer w10: C72.1@1727.92,2676.89 1726.89,2675.86 R239.2@1726.89,2613.35 1729.85,2610.4 C89.1@1793.1,2610.4 1893.1,2610.4 1904.63,2598.87 U11.18@1961.3,2598.87
SWCLK: R4.2 U31.13 | length 169.1
  Top Layer w10: R4.2@1517.43,2146.69 1517.43,2126.97 1523.29,2121.11 1574.42,2121.11 1589.31,2106.23 1589.31,2106.05 1604.19,2091.16 U31.13@1604.19,2043.51
SWDIO: R5.2 U31.12 | length 145.9
  Top Layer w10: R5.2@1566.81,2151.79 1569.46,2149.15 1569.46,2145.6 R5.2@1578.82,2145.6 ; R5.2@1583.16,2155.93 1623.88,2115.21 U31.12@1623.88,2043.51
TOP_ALERT: D14.1 R231.1 R233.2 U31.54 | length 1741.4
  Top Layer w10: U31.54@1917.19,1769.89 1950.57,1769.89 1955.31,1765.16 1977.93,1765.16 v1(1979.78,1763.3) ; v1(3199.36,2274.93) 3201.98,2274.93 3218.21,2258.7 D14.1@3243.47,2258.7 3318.96,2258.7 R231.1@3347.66,2287.4 R233.2@3347.66,2218.34
  Layer 2 w10: v1(1979.78,1763.3) 2025.8,1809.32 2025.8,1829.28 2475.12,2278.6 v1@3194.75,2278.6
TOP_BAT: C64.2 C65.2 C66.2 D15.1 R47.2 R188.2 U10.47 | length 505.2
  Top Layer w10: U10.47@5364.35,2665.12 5399.18,2665.12 5410.99,2676.93 5427.66,2676.93 C66.2@5447.66,2696.93
  Top Layer w20: C66.2@5447.66,2696.93 5513.5,2696.93 C64.2@5517.88,2692.55 5521.75,2688.68 5521.75,2621.46 R188.2@5525.62,2617.59 5525.95,2617.26 5592.17,2617.26 R47.2@5592.51,2616.93 5593.49,2616.93 5608.8,2601.62 C65.2@5608.8,2550 5659.83,2550 D15.1@5706.59,2503.25
TOP_CHG: R259.1 TP7.1 U10.45 | length 1532.7
  Top Layer w10: v1@5286.94,2625.75 U10.45@5364.35,2625.75
  Bottom Layer w10: R259.1@4044.23,2274.93 4052.84,2266.32 4107.9,2266.32 ; TP7.1@4107.9,2214.69 4107.9,2266.32 ; v1(5286.04,2626.49) 5285.84,2626.49 5255.19,2595.84 5255.19,2580.41 5202.35,2527.57 5038.12,2527.57 5024.3,2513.75 5024.3,2513.57 4783.01,2272.28 4782.83,2272.28 4776.87,2266.32 4107.9,2266.32
TOP_CP1: C66.1 CP1.1 R262.1 U10.46 | length 3826.1
  Top Layer w10: U10.46@5364.35,2645.43 v1(5412.65,2645.43) 5441.16,2616.93 C66.1@5447.66,2616.93
  Layer 1 w10: v1(2601.2,1462.57) 2676.29,1537.66 2869.66,1537.66 3487.52,2155.51 v1(3523.62,2155.51)
  Layer 2 w10: v1(3523.62,2155.51) 3526.24,2155.51 3531.46,2160.73 5380.3,2160.73 5485.37,2265.8 5485.37,2577.52 5475.48,2587.41 5422.3,2640.59 5420.12,2640.59 5415.28,2645.43 v1(5412.65,2645.43)
  Bottom Layer w10: CP1.1@2539.76,1419.82 2596.62,1419.82 R262.1@2597.25,1420.45 2601.2,1424.4 v1(2601.2,1462.57)
TOP_DSG: R274.1 U10.43 | length 3294
  Top Layer w10: v1(5278.03,2586.38) U10.43@5364.35,2586.38
  Layer 2 w10: v1(3403.49,1671.4) 3439.22,1707.13 3439.22,2038.44 3543.51,2142.73 5387.76,2142.73 5503.37,2258.34 5503.37,2587.02 5422.12,2668.27 5380.7,2668.27 5298.8,2586.38 v1(5278.03,2586.38)
  Bottom Layer w10: R274.1@3400.18,1623.79 3400.18,1648.79 3401.64,1650.24 3401.64,1669.54 v1(3403.49,1671.4)
TOP_INH: D18.1 R33.1 R34.2 U31.64 | length 1804.5
  Top Layer w10: U31.64@1917.19,1966.74 1918.09,1967.65 1945.31,1967.65 1952.59,1974.92 1978.5,1974.92 2062.66,2059.08 2226.64,2059.08 2349.43,2181.86 2422.47,2181.86 2734.54,2493.94 3037.86,2493.94 3037.99,2493.81 3053.43,2493.81 3168.81,2378.44 v1(3168.81,2377.15) 3171.43,2377.15 3186.72,2361.85 D18.1@3243.09,2361.85 ; R34.2@3230.31,2454.72 3243.09,2441.95 D18.1@3243.09,2361.85 ; R33.1@3348.78,2359.59 3245.35,2359.59 D18.1@3243.09,2361.85
TOP_LD: D29.2 D34.1 D36.1 LD.1 Q64.1 R282.1 R283.2 U10.41 | length 3810.8
  Top Layer w10: U10.41@5364.35,2547.01 5407.17,2547.01 v1(5410.87,2543.31)
  Layer 2 w10: v1(3279.09,1393.7) 3295.91,1410.52 3295.91,1960.1 3514.54,2178.73 3547.62,2178.73 5372.85,2178.73 5465.46,2271.34 5465.46,2516.33 5438.48,2543.31 v1(5410.87,2543.31)
  Bottom Layer w10: D29.2@3263.14,1312.02 3263.14,1378.86 Q64.1@3258.28,1383.73 3258.28,1385.11 3265.02,1391.85 3277.23,1391.85 v1(3279.09,1393.7) 3279.09,1414.29 3297.73,1432.93 3411.2,1432.93 3413.39,1430.73 ; R283.2@3408.11,1388.43 3413.39,1393.7 3413.39,1430.73 ; R282.1@3413.39,1467.77 3413.39,1430.73 ; v1(5410.87,2543.31) 5410.87,2545.93 5426.81,2561.87 D36.1@5426.81,2596.31 5449.61,2619.11 D34.1@5449.61,2682.13 5449.61,2755.97 LD.1@5444.69,2760.9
